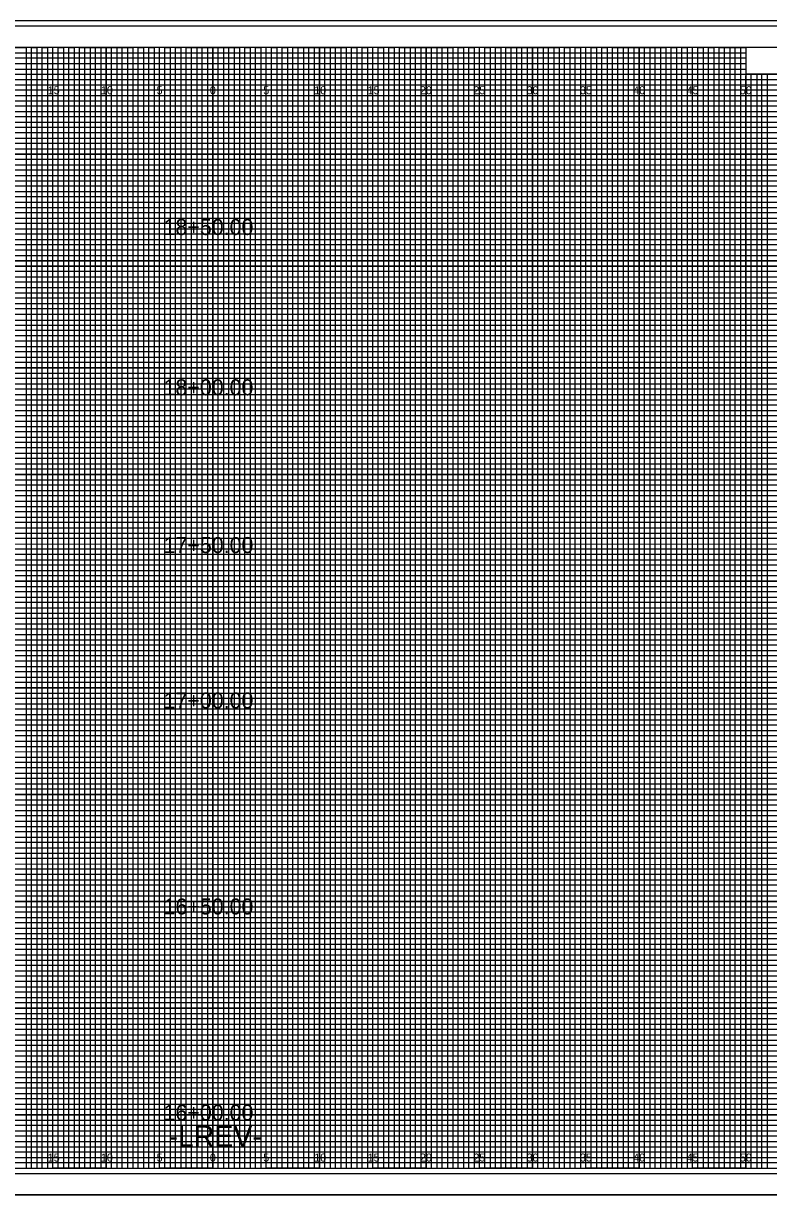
# Model space of a CAD drawing. Extents: x -8 to 533, y -20 to 768.
# Drawn here: x 62.2 to 132.1, y 107.2 to 217.2 of the extents above; entities that cross this region are included whole.
import ezdxf

# ---------------------------------------------------------------- set-up
doc = ezdxf.new("R2010")
doc.units = 0
for name, color, linetype in [('Prop XS Alignment Label', 7, 'Continuous'), ('Prop XS Offset Labels', 7, 'Continuous'), ('Prop XS Station Labels', 7, 'Continuous'), ('Sheet Cross Section CELL', 7, 'Continuous'), ('Sheet Cross Section Grid Major CELL', 7, 'Continuous'), ('Sheet Cross Section Grid Middle CELL', 7, 'Continuous'), ('Sheet Cross Section Grid Minor 1 CELL', 7, 'Continuous'), ('Sheet Cross Section Grid Minor 2 CELL', 7, 'Continuous'), ('Sheet Cutting Line CELL', 7, 'Continuous'), ('Sheet DOT Grid CELL', 7, 'Continuous'), ('Sheet Plot Border Inside CELL', 7, 'Continuous'), ('Sheet Plot Border Outside CELL', 7, 'Continuous'), ('WEI Plot Border', 7, 'Continuous')]:
    doc.layers.add(name, color=color, linetype=linetype)

msp = doc.modelspace()

# ---------------------------------------------------------------- linework, layer by layer
at = {"layer": 'Sheet Cross Section CELL'}
for points in [[(160, 215), (0, 215), (0, 110), (160, 110)], [(140, 215), (130, 215), (130, 212.52), (140, 212.52)]]:
    msp.add_lwpolyline(points, close=True, dxfattribs=at)
at = {"layer": 'Sheet Cross Section Grid Major CELL'}
for p, q in [((65, 215), (60, 215)), ((65, 110), (65, 215)), ((75, 215), (70, 215)), ((70, 215), (70, 110)), ((75, 110), (75, 215)), ((85, 215), (80, 215)), ((80, 215), (80, 110)), ((85, 110), (85, 215)), ((95, 215), (90, 215)), ((90, 215), (90, 110)), ((95, 110), (95, 215)), ((105, 215), (100, 215)), ((100, 215), (100, 110)), ((105, 110), (105, 215)), ((115, 215), (110, 215)), ((110, 215), (110, 110)), ((115, 110), (115, 215)), ((125, 215), (120, 215)), ((120, 215), (120, 110)), ((125, 110), (125, 215)), ((130, 215), (130, 110)), ((70, 110), (65, 110)), ((80, 110), (75, 110)), ((90, 110), (85, 110)), ((100, 110), (95, 110)), ((110, 110), (105, 110)), ((120, 110), (115, 110)), ((130, 110), (125, 110))]:
    msp.add_line(p, q, dxfattribs=at)
for points in [[(0, 210), (160, 210), (160, 205), (0, 205)], [(0, 200), (160, 200), (160, 195), (0, 195)], [(0, 190), (160, 190), (160, 185), (0, 185)], [(0, 180), (160, 180), (160, 175), (0, 175)], [(0, 170), (160, 170), (160, 165), (0, 165)], [(0, 160), (160, 160), (160, 155), (0, 155)], [(0, 150), (160, 150), (160, 145), (0, 145)], [(0, 140), (160, 140), (160, 135), (0, 135)], [(0, 130), (160, 130), (160, 125), (0, 125)], [(0, 120), (160, 120), (160, 115), (0, 115)]]:
    msp.add_lwpolyline(points, dxfattribs=at)
at = {"layer": 'Sheet Cross Section Grid Middle CELL'}
for points in [[(57.5, 215), (62.5, 215), (62.5, 110), (67.5, 110), (67.5, 215), (72.5, 215), (72.5, 110), (77.5, 110), (77.5, 215), (82.5, 215), (82.5, 110), (87.5, 110), (87.5, 215), (92.5, 215), (92.5, 110), (97.5, 110), (97.5, 215), (102.5, 215), (102.5, 110), (107.5, 110), (107.5, 215), (112.5, 215), (112.5, 110), (117.5, 110), (117.5, 215), (122.5, 215), (122.5, 110), (127.5, 110), (127.5, 215), (129.97, 215), (130, 215), (130, 212.5), (132.5, 212.5)], [(0, 212.5), (137.5, 212.5)], [(0, 202.5), (160, 202.5), (160, 207.5), (0, 207.5)], [(0, 192.5), (160, 192.5), (160, 197.5), (0, 197.5)], [(0, 182.5), (160, 182.5), (160, 187.5), (0, 187.5)], [(0, 172.5), (160, 172.5), (160, 177.5), (0, 177.5)], [(0, 162.5), (160, 162.5), (160, 167.5), (0, 167.5)], [(0, 152.5), (160, 152.5), (160, 157.5), (0, 157.5)], [(0, 142.5), (160, 142.5), (160, 147.5), (0, 147.5)], [(0, 132.5), (160, 132.5), (160, 137.5), (0, 137.5)], [(0, 122.5), (160, 122.5), (160, 127.5), (0, 127.5)], [(0, 112.5), (160, 112.5), (160, 117.5), (0, 117.5)]]:
    msp.add_lwpolyline(points, dxfattribs=at)
at = {"layer": 'Sheet Cross Section Grid Minor 1 CELL'}
for p, q in [((0, 214.5), (130, 214.5)), ((130, 213.99), (0, 213.99)), ((0, 213.5), (130, 213.5)), ((130, 214.5), (130, 213.99)), ((130, 213.5), (130, 212.94)), ((130, 212.94), (0, 212.94)), ((0, 212), (160, 212))]:
    msp.add_line(p, q, dxfattribs=at)
for points in [[(0, 211.5), (135, 211.5), (160, 211.5), (160, 211), (0, 211)], [(0, 210.5), (160, 210.5), (160, 209.5), (0, 209.5)], [(0, 209), (160, 209), (160, 208.5), (0, 208.49)], [(0, 208), (160, 208), (160, 207), (0, 207)], [(0, 206.5), (160, 206.5), (160, 206), (0, 206)], [(0, 205.5), (160, 205.5), (160, 204.5), (0, 204.5)], [(0, 204), (160, 204), (160, 203.5), (0, 203.5)], [(0, 203), (160, 203), (160, 202), (0, 202)], [(0, 201.5), (160, 201.5), (160, 201), (0, 201)], [(0, 200.5), (160, 200.5), (160, 199.5), (0, 199.5)], [(0, 199), (160, 199), (160, 198.5), (0, 198.5)], [(0, 198), (160, 198), (160, 196.97), (160, 196.5), (160, 196), (0, 196)], [(0, 197), (160, 197), (160, 196.5), (0, 196.5)], [(0, 195.5), (160, 195.5), (160, 194.5), (0, 194.52)], [(0, 194.52), (160, 194.5), (160, 194), (0, 194)], [(0, 193.5), (160, 193.5), (160, 193), (0, 193)], [(0, 192), (160, 192), (160, 191.5), (0, 191.5)], [(0, 191), (160, 191), (160, 190.5), (0, 190.5)], [(-0.04, 189.44), (160, 189.44), (160, 188.94), (-0.04, 188.94)], [(0, 188.5), (160, 188.5), (160, 188), (0, 188)], [(0, 187), (160, 187), (160, 186.5), (0, 186.5)], [(0, 186), (160, 186), (160, 185.5), (0, 185.5)], [(0, 184.5), (160, 184.5), (160, 184), (0, 184)], [(0, 183.5), (160, 183.5), (160, 183), (0, 183)], [(0, 182), (160, 182), (160, 181.5), (0, 181.5)], [(0, 181), (160, 181), (160, 180.5), (0, 180.5)], [(0, 179.5), (160, 179.5), (160, 178.99), (0, 179)], [(0, 178.5), (160, 178.5), (160, 178), (0, 178)], [(0, 177), (160, 177), (160, 176.5), (0, 176.5)], [(0, 176), (160, 176), (160, 175.5), (0, 175.5)], [(0, 174.5), (160, 174.5), (160, 174), (0, 174)], [(0, 173.5), (160, 173.5), (160, 173), (0, 173)], [(0, 172), (160, 172), (160, 171.5), (0, 171.5)], [(0, 171), (160, 171), (160, 170.5), (0, 170.5)], [(0, 169.5), (160, 169.5), (160, 169), (0, 169)], [(0, 168.5), (160.03, 168.46), (160, 168), (0, 168)], [(0, 167), (160, 167), (160, 166.5), (0, 166.5)], [(0, 166), (160, 166), (160, 165.5), (0, 165.5)], [(0, 164.5), (160, 164.5), (160, 164), (0, 164)], [(0, 163.5), (160, 163.5), (160, 163), (0, 163)], [(0, 162), (160, 162), (160, 161.5), (0, 161.5)], [(0, 161), (160, 161), (160, 160.5), (0, 160.5)], [(0, 159.5), (160, 159.5), (160, 159), (0, 159)], [(0, 158.5), (160, 158.5), (160, 158), (0, 158)], [(0, 157), (160, 157), (160, 156.5), (0, 156.5)], [(0, 156), (160, 156), (160, 155.5), (0, 155.5)], [(0, 154.5), (160, 154.5), (160, 154), (0, 154)], [(0, 153.5), (160, 153.5), (160, 153), (0, 153)], [(0, 152), (160, 152), (160, 151.5), (0, 151.5)], [(0, 151), (160, 151), (160, 150.5), (0, 150.5)], [(0, 149.5), (160, 149.5), (160, 148.99), (0, 149)], [(0, 148.5), (160, 148.5), (160, 148), (0, 148)], [(0, 147), (160, 147), (160, 146.5), (0, 146.5)], [(0, 146), (160, 146), (160, 145.5), (0, 145.5)], [(0, 144.5), (160, 144.5), (160, 144), (0, 144)], [(0, 143.5), (160, 143.5), (160, 143), (0, 143)], [(0, 142), (160, 142), (160, 141.5), (0, 141.5)], [(0, 141), (160, 141), (160, 140.5), (0, 140.5)], [(0, 139.5), (160, 139.5), (160, 139), (0, 139)], [(0, 138.5), (160.03, 138.46), (160, 138), (0, 138)], [(0, 137), (160, 137), (160, 136.5), (0, 136.5)], [(0, 136), (160, 136), (160, 135.5), (0, 135.5)], [(0, 134.5), (160, 134.5), (160, 134), (0, 134)], [(0, 133.5), (160, 133.5), (160, 133), (0, 133)], [(0, 132), (160, 132), (160, 131.5), (0, 131.5)], [(0, 131), (160, 131), (160, 130.5), (0, 130.5)], [(0, 129.5), (160, 129.5), (160, 129), (0, 129)], [(0, 128.5), (160, 128.5), (160, 128), (0, 128)], [(0, 127), (160, 127), (160, 126.5), (0, 126.5)], [(0, 126), (160, 126), (160, 125.5), (0, 125.5)], [(0, 124.5), (160, 124.5), (160, 124), (0, 124)], [(0, 123.5), (160, 123.5), (160, 123), (0, 123)], [(0, 122), (160, 122), (160, 121.5), (0, 121.5)], [(0, 121), (160, 121), (160, 120.5), (0, 120.5)], [(0, 119.5), (160, 119.5), (160, 119), (0, 119)], [(0, 118.5), (160, 118.5), (160, 118), (0, 118)], [(0, 117), (160, 117), (160, 116.5), (0, 116.5)], [(0, 116), (160, 116), (160, 115.5), (0, 115.5)], [(0, 114.5), (160, 114.5), (160, 114), (0, 114)], [(0, 113.5), (160, 113.5), (160, 113), (0, 113)], [(0, 112), (160, 112), (160, 111.5), (0, 111.5)], [(0, 111), (160, 111), (160, 110.5), (0, 110.5)]]:
    msp.add_lwpolyline(points, dxfattribs=at)
at = {"layer": 'Sheet Cross Section Grid Minor 2 CELL'}
for points in [[(62.5, 110), (63, 110), (63, 215), (63.5, 215), (63.5, 110)], [(63.5, 110), (64, 110), (64, 215), (64.5, 215), (64.5, 110)], [(65, 110), (65.5, 110), (65.5, 215), (66, 215), (66, 110)], [(66, 110), (66.5, 110), (66.5, 215), (67, 215), (67, 110)], [(67.5, 110), (68, 110), (68, 215), (68.5, 215), (68.5, 110)], [(68.5, 110), (69, 110), (69, 215), (69.5, 215), (69.5, 110)], [(70, 110), (70.5, 110), (70.5, 215), (71, 215), (71, 110)], [(71, 110), (71.5, 110), (71.5, 215), (72, 215), (72, 110)], [(72.5, 110), (73, 110), (73, 215), (73.5, 215), (73.5, 110)], [(73.5, 110), (74, 110), (74, 215), (74.5, 215), (74.5, 110)], [(75, 110), (75.5, 110), (75.5, 215), (76, 215), (76, 110)], [(76, 110), (76.5, 110), (76.5, 215), (77, 215), (77, 110)], [(77.5, 110), (78, 110), (78, 215), (78.5, 215), (78.5, 110)], [(78.5, 110), (79, 110), (79, 215), (79.5, 215), (79.5, 110)], [(80, 110), (80.5, 110), (80.5, 215), (81, 215), (81, 110)], [(81, 110), (81.5, 110), (81.5, 215), (82, 215), (82, 110)], [(82.5, 110), (83, 110), (83, 215), (83.5, 215), (83.5, 110)], [(83.5, 110), (84, 110), (84, 215), (84.5, 215), (84.5, 110)], [(85, 110), (85.5, 110), (85.5, 215), (86, 215), (86, 110)], [(86, 110), (86.5, 110), (86.5, 215), (87, 215), (87, 110)], [(87.5, 110), (88, 110), (88, 215), (88.5, 215), (88.5, 110)], [(88.5, 110), (89, 110), (89, 215), (89.5, 215), (89.5, 110)], [(90, 110), (90.5, 110), (90.5, 215), (91, 215), (91, 110)], [(91, 110), (91.5, 110), (91.5, 215), (92, 215), (92, 110)], [(92.5, 110), (93, 110), (93, 215), (93.5, 215), (93.5, 110)], [(93.5, 110), (94, 110), (94, 215), (94.5, 215), (94.5, 110)], [(95, 110), (95.5, 110), (95.5, 215), (96, 215), (96, 110)], [(96, 110), (96.5, 110), (96.5, 215), (97, 215), (97, 110)], [(97.5, 110), (98, 110), (98, 215), (98.5, 215), (98.5, 110)], [(98.5, 110), (99, 110), (99, 215), (99.5, 215), (99.5, 110)], [(100, 110), (100.5, 110), (100.5, 215), (101, 215), (101, 110)], [(101, 110), (101.5, 110), (101.5, 215), (102, 215), (102, 110)], [(102.5, 110), (103, 110), (103, 215), (103.5, 215), (103.5, 110)], [(103.5, 110), (104, 110), (104, 215), (104.5, 215), (104.5, 110)], [(105, 110), (105.5, 110), (105.5, 215), (106, 215), (106, 110)], [(106, 110), (106.5, 110), (106.5, 215), (107, 215), (107, 110)], [(107.5, 110), (108, 110), (108, 215), (108.5, 215), (108.5, 110)], [(108.5, 110), (109, 110), (109, 215), (109.5, 215), (109.5, 110)], [(110, 110), (110.5, 110), (110.5, 215), (111, 215), (111, 110)], [(111, 110), (111.5, 110), (111.5, 215), (112, 215), (112, 110)], [(112.5, 110), (113, 110), (113, 215), (113.5, 215), (113.5, 110)], [(113.5, 110), (114, 110), (114, 215), (114.5, 215), (114.5, 110)], [(115, 110), (115.5, 110), (115.5, 215), (116, 215), (116, 110)], [(116, 110), (116.5, 110), (116.5, 215), (117, 215), (117, 110)], [(117.5, 110), (118, 110), (118, 215), (118.5, 215), (118.5, 110)], [(118.5, 110), (119, 110), (119, 215), (119.5, 215), (119.5, 110)], [(120, 110), (120.5, 110), (120.5, 215), (121, 215), (121, 110)], [(121, 110), (121.5, 110), (121.5, 215), (122, 215), (122, 110)], [(122.5, 110), (123, 110), (123, 215), (123.5, 215), (123.5, 110)], [(123.5, 110), (124, 110), (124, 215), (124.5, 215), (124.5, 110)], [(125, 110), (125.5, 110), (125.5, 215), (126, 215), (126, 110)], [(126, 110), (126.5, 110), (126.5, 215), (127, 215), (127, 110)], [(127.5, 110), (128, 110), (128, 215), (128.5, 215), (128.5, 110)], [(128.5, 110), (129, 110), (129, 215), (129.5, 215), (129.5, 110)], [(130, 110), (130.5, 110), (130.5, 212.5), (131.01, 212.5), (131.01, 110)], [(131, 110), (131.5, 110), (131.5, 212.5), (132, 212.5), (132, 110)]]:
    msp.add_lwpolyline(points, dxfattribs=at)
at = {"layer": 'Sheet Cutting Line CELL'}
for p, q in [((161.65, 217), (-6.7, 217)), ((-6.7, 107.5), (161.65, 107.5))]:
    msp.add_line(p, q, dxfattribs=at)
at = {"layer": 'Sheet DOT Grid CELL'}
for p, q in [((65, 110), (65, 215)), ((70, 110), (70, 215)), ((75, 110), (75, 215)), ((80, 110), (80, 215)), ((85, 110), (85, 215)), ((90, 110), (90, 215)), ((95, 110), (95, 215)), ((100, 110), (100, 215)), ((105, 110), (105, 215)), ((110, 110), (110, 215)), ((115, 110), (115, 215)), ((120, 110), (120, 215)), ((125, 110), (125, 215)), ((130, 110), (130, 212.34)), ((0, 210), (160, 210)), ((0, 205), (160, 205)), ((0, 200), (160, 200)), ((0, 195), (160, 195)), ((0, 190), (160, 190)), ((0, 185), (160, 185)), ((0, 180), (160, 180)), ((0, 175), (160, 175)), ((0, 170), (160, 170)), ((0, 165), (160, 165)), ((0, 160), (160, 160)), ((0, 155), (160, 155)), ((0, 150), (160, 150)), ((0, 145), (160, 145)), ((0, 140), (160, 140)), ((0, 135), (160, 135)), ((0, 130), (160, 130)), ((0, 125), (160, 125)), ((0, 120), (160, 120)), ((0, 115), (160, 115))]:
    msp.add_line(p, q, dxfattribs=at)
at = {"layer": 'Sheet Plot Border Inside CELL'}
msp.add_lwpolyline([(-5.4, 109.5), (161.2, 109.5), (161.2, 215), (-5.4, 215)], close=True, dxfattribs=at)
at = {"layer": 'Sheet Plot Border Outside CELL'}
msp.add_lwpolyline([(-6.7, 107.5), (161.65, 107.5), (161.65, 217), (-6.7, 217)], close=True, dxfattribs=at)
at = {"layer": 'WEI Plot Border'}
for points in [[(-7.5, 107.5), (162.5, 107.5), (162.5, 217.5), (-7.5, 217.5)], [(-7.5, -2.5), (162.5, -2.5), (162.5, 107.5), (-7.5, 107.5)]]:
    msp.add_lwpolyline(points, close=True, dxfattribs=at)

# ---------------------------------------------------------------- texts
at = {"layer": 'Prop XS Alignment Label'}
msp.add_text('-LREV-', height=2, dxfattribs=at).set_placement((75.84, 112))
at = {"layer": 'Prop XS Offset Labels'}
for s, p in [('15', (64.53, 210.62)), ('10', (69.52, 210.62)), ('5', (74.74, 210.62)), ('0', (79.73, 210.62)), ('0', (79.73, 210.62)), ('5', (84.74, 210.62)), ('10', (89.52, 210.62)), ('15', (94.53, 210.62)), ('20', (99.43, 210.62)), ('25', (104.44, 210.62)), ('30', (109.43, 210.62)), ('35', (114.44, 210.62)), ('40', (119.43, 210.62)), ('45', (124.44, 210.62)), ('50', (129.43, 210.62)), ('15', (64.53, 110.62)), ('10', (69.52, 110.62)), ('5', (74.74, 110.62)), ('0', (79.73, 110.62)), ('0', (79.73, 110.62)), ('5', (84.74, 110.62)), ('10', (89.52, 110.62)), ('15', (94.53, 110.62)), ('20', (99.43, 110.62)), ('25', (104.44, 110.62)), ('30', (109.43, 110.62)), ('35', (114.44, 110.62)), ('40', (119.43, 110.62)), ('45', (124.44, 110.62)), ('50', (129.43, 110.62))]:
    msp.add_text(s, height=0.75, dxfattribs=at).set_placement(p)
at = {"layer": 'Prop XS Station Labels'}
for s, p in [('18+50.00', (75.39, 197.43)), ('18+00.00', (75.39, 182.41)), ('17+50.00', (75.39, 167.63)), ('17+00.00', (75.39, 153.07)), ('16+50.00', (75.39, 133.77)), ('16+00.00', (75.39, 114.46))]:
    msp.add_text(s, height=1.5, dxfattribs=at).set_placement(p)

doc.saveas('drawing.dxf')
